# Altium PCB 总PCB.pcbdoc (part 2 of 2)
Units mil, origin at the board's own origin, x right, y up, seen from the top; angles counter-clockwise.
Board outline 1771.65 x 3543.31 mil, 2 copper layers (Top Layer, Bottom Layer), stack 62.205 mil thick; 115 components, 80 nets, 419 pads, 214 vias.
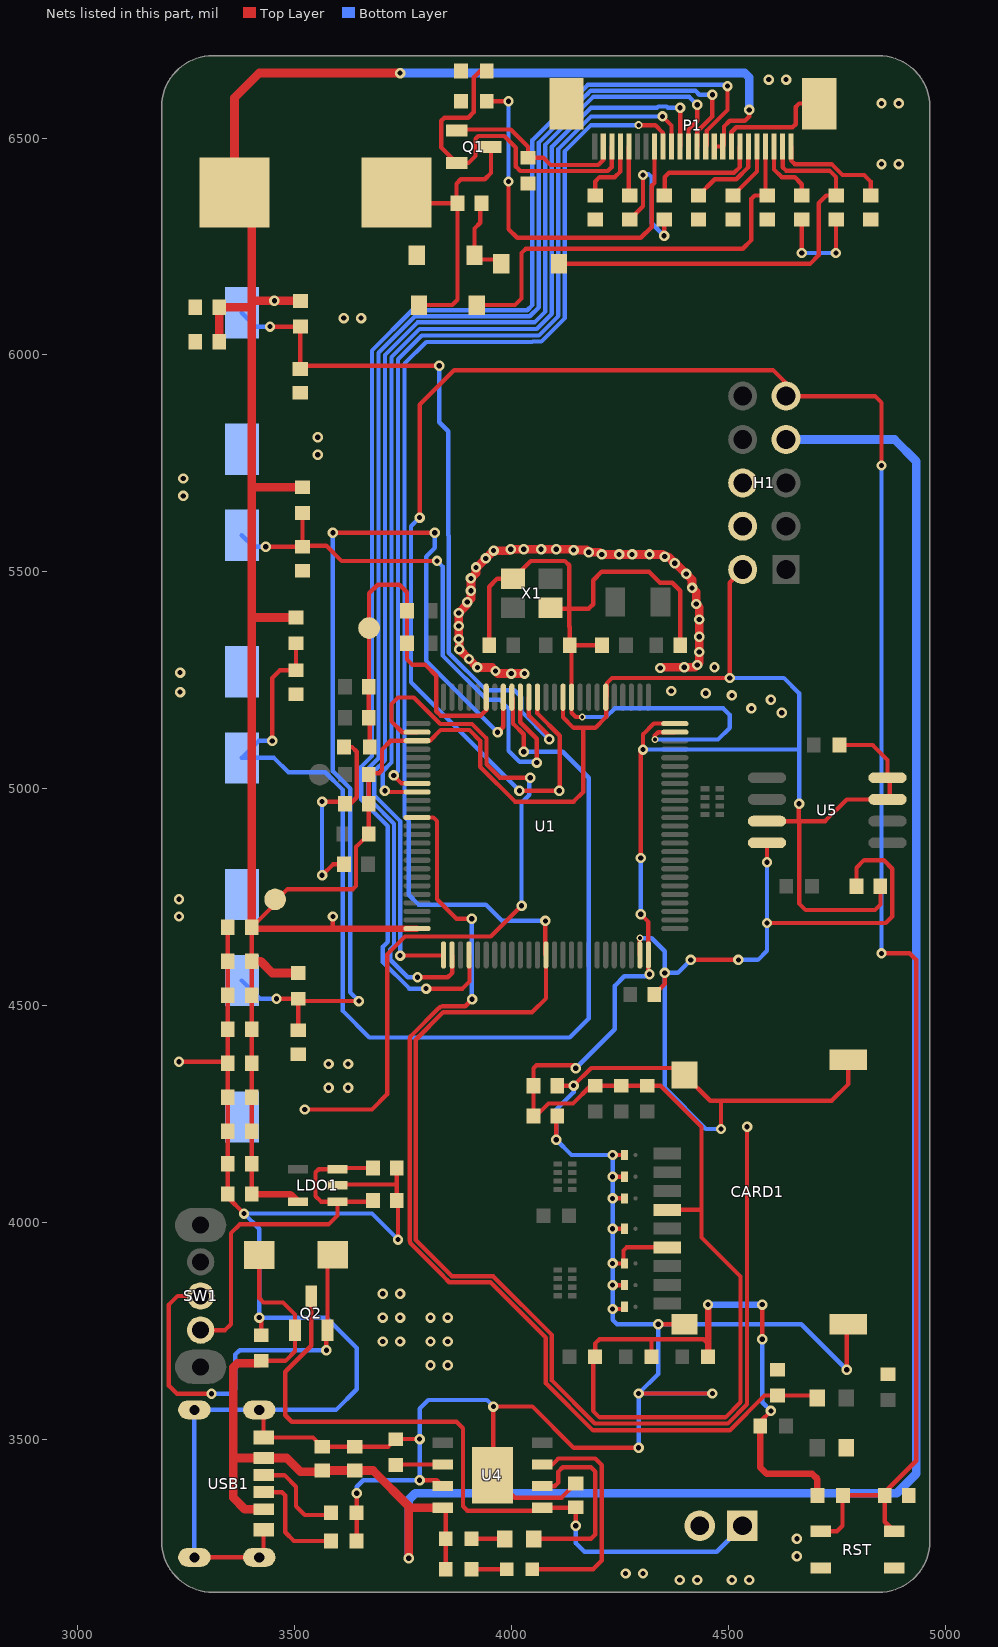
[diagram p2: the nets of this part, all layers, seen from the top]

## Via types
v1: diameter 24.02, hole 12.01, Top Layer to Bottom Layer, 210 vias
v2: diameter 16, hole 9, Top Layer to Bottom Layer, 3 vias
v3: diameter 18, hole 10, Top Layer to Bottom Layer, 1 vias

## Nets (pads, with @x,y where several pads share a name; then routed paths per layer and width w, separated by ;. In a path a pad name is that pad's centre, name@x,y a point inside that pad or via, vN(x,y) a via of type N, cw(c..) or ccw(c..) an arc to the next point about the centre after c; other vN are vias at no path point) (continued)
$1I11\NRST: C37.1 H1.9 R12.1 RST.3 RST.4 U1.14 | length 5412.9
  Top Layer w10: v1(3788.47,5625) 3788.47,5885 3868.47,5965 4603.47,5965 4633.47,5935 H1.9@4633.47,5905 4838.47,5905 4853.47,5890 v1(4853.47,5745) ; v1(4018.47,4995) v1(4110.54,4995) 4111.46,4995.92 4111.46,5122.01 4060.06,5173.41 U1.14@4060.06,5210.8 ; RST.4@4713.82,3287.32 4750.79,3287.32 4763.47,3300 4763.47,3368.55 R12.1@4765.02,3370.1 4860.8,3370.1 C37.1@4860.91,3370 ; v1(4853.47,4620) 4918.47,4620 4933.47,4605 4933.47,3450 4860.91,3377.44 C37.1@4860.91,3370 ; RST.3@4883.11,3287.32 4860.91,3309.53 C37.1@4860.91,3370
  Bottom Layer w10: v1(3788.47,5625) 3768.47,5605 3768.47,5245 v1(4018.47,4995) ; v1(4853.47,4620) v1(4853.47,5745)
$1I11\PB2(BOOT1): LED3.1 R18.2 U1.37 | length 2382.3
  Top Layer w10: U1.37@3782.51,4933.24 3820.23,4933.24 3828.47,4925 3828.47,4745 3873.47,4700 v1(3908.47,4700) ; v1(3909.45,4514.02) 3893.47,4498.03 3842.66,4498.03 ccw(c3842.66,4484.02) 3832.75,4493.93 3769.54,4430.72 ccw(c3779.45,4420.81) 3765.44,4420.81 3765.44,3959.19 ccw(c3779.45,3959.19) 3769.54,3949.28 3843.47,3875.36 3843.47,3875 3856.97,3861.5 3951.97,3861.5 4079.45,3734.02 4079.45,3629.02 4188.47,3520 4503.47,3520 4583.81,3600.34 R18.2@4613.47,3600.34 4699.66,3600.34 LED3.1@4705,3595
  Bottom Layer w10: v1(3908.47,4700) 3908.47,4515 v1(3909.45,4514.02)
$1I11\PC0: C38.2 R13.1 SW3.2 U1.15 | length 1690.1
  Top Layer w10: v1(3443.47,6065.34) R13.1@3513.47,6065.34 C38.2@3513.47,5967.56 3520.91,5975 v1(3833.47,5975) ; U1.15@4040.38,5210.8 4040.38,5168.09 4087.21,5121.26 v1(4087.21,5113.74)
  Bottom Layer w10: SW3.2@3378.47,6097.48 3410.61,6065.34 v1(3443.47,6065.34) ; v1(3833.47,5975) 3833.47,5845 3854.45,5824.02 3854.45,5584.19 3855.48,5583.17 3855.48,5312.99 3941.4,5227.07 4006.4,5227.07 4023.47,5210 4023.47,5177.48 v1(4087.21,5113.74)
$1I11\PC1: C39.2 R14.1 SW4.2 U1.16 | length 1320.6
  Top Layer w10: v1(3433.47,5557.56) C39.2@3518.47,5557.56 ; R14.1@3518.47,5635.34 C39.2@3518.47,5557.56 ; v1(3828.47,5525) 3608.47,5525 3573.47,5560 3520.91,5560 C39.2@3518.47,5557.56 ; U1.16@4020.69,5210.8 4020.69,5152.78 4058.47,5115 v1(4058.47,5060)
  Bottom Layer w10: SW4.2@3378.47,5584.15 3405.05,5557.56 v1(3433.47,5557.56) ; v1(3828.47,5525) 3841.46,5512.01 3841.46,5307.01 3943.47,5205 3973.47,5205 3993.47,5185 3993.47,5087.48 4018.94,5062.01 4056.46,5062.01 v1(4058.47,5060)
$1I11\PC2: C40.2 R15.1 SW5.2 U1.17 | length 2607.4
  Top Layer w10: v1(3448.47,5110) 3448.47,5255 3466.03,5272.56 C40.2@3503.47,5272.56 R15.1@3503.47,5335.34 ; U1.17@4001.01,5210.8 4003.8,5208.01 4003.8,5149.85 4028.47,5125.18 v1(4028.47,5085)
  Bottom Layer w10: v1(3448.47,5110) 3417.65,5110 SW5.2@3378.47,5070.81 3452.65,5070.81 3485.91,5037.56 3570.91,5037.56 3611.46,4997.01 3611.46,4487.01 3672.48,4425.98 4134.45,4425.98 4178.47,4470 4178.47,5025 4118.47,5085 v1(4028.47,5085)
$1I11\PC3: C41.2 R16.1 SW6.2 U1.18 | length 2325.5
  Top Layer w10: v1(3458.47,4515.34) R16.1@3508.47,4515.34 ; C41.2@3508.47,4442.56 R16.1@3508.47,4515.34 ; v1(3588.47,5590) v1(3823.47,5590) ; v1(3648.47,4510) 3513.81,4510 R16.1@3508.47,4515.34 ; v1(3968.24,5129.78) 3981.32,5142.85 U1.18@3981.32,5210.8
  Bottom Layer w10: SW6.2@3378.47,4557.48 3420.61,4515.34 v1(3458.47,4515.34) ; v1(3588.47,5590) 3588.47,5040 3628.47,5000 3628.47,4530 v1(3648.47,4510) ; v1(3823.47,5590) 3823.47,5555 3803.47,5535 3803.47,5294.55 v1(3968.24,5129.78)
$1I12\$1N70: C45.2 P1.24 | length 268.3
  Top Layer w10: P1.24@4645.1,6480.78 4645.1,6448.36 4653.47,6440 4738.47,6440 4763.47,6415 4813.47,6415 4828.47,6400 C45.2@4828.47,6367.56
$1I12\$1N71: C35.2 P1.22 | length 157.3
  Top Layer w10: P1.22@4605.71,6480.78 4605.71,6427.76 4623.47,6410 4653.47,6410 4669.72,6393.75 C35.2@4669.72,6367.56
$1I12\$1N72: C33.2 P1.20 | length 136.2
  Top Layer w10: C33.2@4510.97,6367.56 4566.34,6422.94 P1.20@4566.34,6480.78
$1I12\$1N73: C32.2 P1.19 | length 189.8
  Top Layer w10: C32.2@4431.59,6367.56 4469.03,6405 4518.47,6405 4546.57,6433.1 P1.19@4546.57,6480.78
$1I12\$1N74: C29.2 P1.18 | length 273.4
  Top Layer w10: C29.2@4352.22,6367.56 4353.47,6368.81 4353.47,6410 4363.47,6420 4513.47,6420 4526.89,6433.43 P1.18@4526.89,6480.78
$1I12\$1N84: C27.2 P1.5 | length 114
  Top Layer w10: P1.5@4271,6480.78 4271,6369.4 C27.2@4272.84,6367.56
$1I12\$1N85: C25.2 P1.4 | length 157.7
  Top Layer w10: C25.2@4193.47,6367.56 4193.47,6400 4203.47,6410 4238.47,6410 4251.32,6422.85 P1.4@4251.32,6480.78
$1I12\$1N94: C28.2 D4.2 L2.2 Q1.3 | length 663.7
  Top Layer w10: L2.2@3735.47,6375 3760.47,6350 C28.2@3875.91,6350 ; D4.2@3786.84,6115 3863.47,6115 3875.91,6127.44 C28.2@3875.91,6350 ; Q1.3@3952.84,6480 3952.84,6419.37 3938.47,6405 3883.47,6405 3873.47,6395 3873.47,6352.44 C28.2@3875.91,6350
$1I12\$1N95: C28.1 D2.2 D3.1 | length 196.6
  Top Layer w10: C28.1@3931.03,6350 3928.47,6347.44 3928.47,6305 3915.1,6291.63 D2.2@3915.1,6230 3925.1,6220 3966.84,6220 D3.1@3976.84,6210
$1I12\BS: P1.8 R3.2 | length 882.5
  Top Layer w10: R3.2@3943.13,6585 v1(3993.47,6585) ; v1(3993.47,6400) 3993.47,6290 4013.47,6270 4298.47,6270 4323.47,6295 4323.47,6390 4330.06,6396.6 P1.8@4330.06,6480.78
  Bottom Layer w10: v1(3993.47,6400) v1(3993.47,6585)
$1I12\BUS: P1.9 U1.63 | length 5296.9
  Top Layer w10: v1(4078.47,4695) 4078.47,4617.6 U1.63@4079.75,4616.32 4079.75,4516.28 4047.48,4484.02 3842.66,4484.02 3779.45,4420.81 3779.45,3959.19 3863.13,3875.51 3957.95,3875.51 4093.47,3740 4093.47,3635 4192.48,3535.98 4499.27,3535.98 4543.47,3580.18 v1(4543.47,4220) ; v3(4293.47,6530) 4331.81,6530 4349.74,6512.07 P1.9@4349.74,6480.78
  Bottom Layer w10: v1(4078.47,4695) 3978.47,4695 3940.97,4732.5 3785.97,4732.5 3763.47,4755 3763.47,4925 3753.47,4935 3753.47,5980 3803.47,6030 4048.47,6030 4049.45,6030.98 4069.27,6030.98 4123.47,6085.18 4123.47,6470 4183.47,6530 v3(4293.47,6530)
$1I12\CS: P1.12 U1.51 | length 2824.7
  Top Layer w10: v1(3743.47,4615) 3842.21,4615 U1.51@3843.53,4616.32 ; P1.12@4408.8,6480.78 4408.47,6481.12 4408.47,6520 4428.47,6540 v1(4428.47,6576.74)
  Bottom Layer w10: v1(3743.47,4615) 3743.47,4925 3683.47,4985 3683.47,5040 3708.47,5065 3708.47,6000 3783.47,6075 4053.47,6075 4078.47,6100 4078.47,6485 4188.47,6595 4410.2,6595 v1(4428.47,6576.74)
$1I12\D/C: P1.11 U1.34 | length 2306.6
  Top Layer w10: v1(3708.47,4995) 3711.17,4992.3 U1.34@3782.51,4992.3 ; P1.11@4389.11,6480.78 v1(4389.11,6570)
  Bottom Layer w10: v1(3708.47,4995) 3703.47,5000 3703.47,5040 3723.47,5060 3723.47,5995 3788.47,6060 4058.47,6060 4093.47,6095 4093.47,6480 4183.47,6570 4335.95,6570 4338.94,6572.99 4357.99,6572.99 4360.98,6570 v1(4389.11,6570)
$1I12\GDR: P1.2 Q1.1 R11.2 | length 424.1
  Top Layer w10: Q1.1@3874.1,6517.4 3876.7,6520 3998.47,6520 4038.47,6480 R11.2@4038.47,6454.66 4038.81,6455 4073.47,6455 4090.44,6438.03 4200.5,6438.03 4211.95,6449.49 P1.2@4211.95,6480.78
$1I12\PREVGH: C34.2 D4.1 P1.21 | length 1007
  Top Layer w10: D4.1@3920.1,6115 4008.47,6115 4023.47,6130 4023.47,6235 4033.47,6245 4533.47,6245 4553.47,6265 4553.47,6360 4561.03,6367.56 C34.2@4590.34,6367.56 4586.04,6371.86 P1.21@4586.04,6480.78
$1I12\PREVGL: C36.2 D3.2 P1.23 | length 997.6
  Top Layer w10: D3.2@4110.1,6210 4688.47,6210 4708.47,6230 4708.47,6350 4726.03,6367.56 C36.2@4749.09,6367.56 4748.47,6368.19 4748.47,6410 4733.47,6425 4633.47,6425 4625.41,6433.06 P1.23@4625.41,6480.78
$1I12\RES: P1.10 U1.33 | length 2170.6
  Top Layer w10: v1(3728.97,5030.51) 3728.97,5029.49 3746.48,5011.99 U1.33@3782.51,5011.99 ; v1(4348.47,6550) 4369.43,6529.03 P1.10@4369.43,6480.78
  Bottom Layer w10: v1(3728.97,5030.51) 3738.47,5040 3738.47,5990 3793.47,6045 4063.47,6045 4108.47,6090 4108.47,6475 4183.47,6550 v1(4348.47,6550)
$1I12\RESE: P1.3 Q1.2 R4.1 | length 828.5
  Top Layer w10: R4.1@3943.13,6655 3928.47,6655 3913.47,6640 3913.47,6560 3900.54,6547.07 3845.54,6547.07 3838.47,6540 3838.47,6478.23 Q1.2@3874.1,6442.6 3901.07,6442.6 3917.25,6458.78 3917.25,6498.33 3923.68,6504.76 3973.23,6504.76 3973.47,6505 3983.47,6505 4010.48,6477.99 4010.48,6434.23 4020.69,6424.02 4222.48,6424.02 4231.63,6433.16 P1.3@4231.63,6480.78
$1I12\SCK: P1.13 U1.52 | length 3023.6
  Top Layer w10: v1(3783.47,4565) 3853.47,4565 3863.47,4575 3863.47,4616.06 U1.52@3863.21,4616.32 ; P1.13@4428.48,6480.78 4428.48,6515.02 4463.47,6550 v1(4463.47,6600)
  Bottom Layer w10: v1(3783.47,4565) 3760.95,4565 3720.48,4605.48 3720.48,4628.89 3729.45,4637.87 3729.45,4919.02 3678.47,4970 3678.47,4970.18 3669.45,4979.19 3669.45,5045.81 3678.47,5054.82 3678.47,5055 3693.47,5070 3693.47,6005 3777.48,6089.02 4042.48,6089.02 4063.47,6110 4063.47,6490 4173.47,6600 4173.65,6600 4182.66,6609.02 4424.46,6609.02 4433.48,6600 v1(4463.47,6600)
$1I12\SDA: P1.14 U1.54 | length 3202.5
  Top Layer w10: v1(3803.47,4538.69) 3887.16,4538.69 3903.47,4555 3903.47,4615.43 U1.54@3902.58,4616.32 ; P1.14@4448.17,6480.78 4450.81,6483.43 4450.81,6517.35 4498.47,6565 v1(4498.47,6620)
  Bottom Layer w10: v1(3803.47,4538.69) 3764.78,4538.69 3703.47,4600 3703.47,4635 3715.25,4646.78 3715.25,4913.22 3653.47,4975 3653.47,5050 3678.47,5075 3678.47,6010 3771.5,6103.03 4036.5,6103.03 4048.47,6115 4048.47,6495 4176.46,6622.99 4495.48,6622.99 v1(4498.47,6620)
$1I13\$1N65: R6.1 USB1.B5 | length 251.8
  Top Layer w10: USB1.B5@3428.46,3377.52 3470.95,3377.52 3478.47,3370 3478.47,3285 3498.47,3265 R6.1@3583.81,3265
$1I13\$1N66: R7.1 USB1.A5 | length 221.8
  Top Layer w10: USB1.A5@3428.46,3416.89 3476.58,3416.89 3503.47,3390 3503.47,3345 3523.47,3325 3578.81,3325 R7.1@3583.81,3330
$1I13\$1N69: R5.2 U4.2 | length 109.8
  Top Layer w10: R5.2@3733.47,3445.34 3737.32,3441.49 U4.2@3841.69,3441.49
$1I13\$1N73: LED1.1 R8.2 | length 76.9
  Top Layer w10: R8.2@3908.13,3270 LED1.1@3985,3270
$1I13\$1N74: LED2.2 R9.2 | length 80.8
  Top Layer w10: R9.2@3908.13,3200 LED2.2@3988.98,3199.99
$1I13\$1N75: LED1.2 U4.6 | length 450.3
  Top Layer w10: LED1.2@4051.93,3270 4183.47,3270 4193.47,3280 4193.47,3425 4183.47,3435 4118.47,3435 4108.47,3425 4108.47,3400 4099.96,3391.49 U4.6@4070.69,3391.49
$1I13\$1N76: LED2.1 U4.7 | length 538.4
  Top Layer w10: LED2.1@4047.96,3200.01 4188.47,3200 4208.47,3220 4208.47,3440 4193.47,3455 4108.47,3455 4094.96,3441.49 U4.7@4070.69,3441.49
$1I13\NET_BAT: C26.2 CN1.1 Q2.3 U4.5 | length 1669.5
  Top Layer w10: Q2.3@3538.47,3829.37 3538.47,3715 3478.47,3655 3478.47,3555 3493.47,3540 3873.47,3540 3888.47,3525 3888.47,3345 3898.47,3335 4064.2,3335 U4.5@4070.69,3341.49 4147.52,3341.49 C26.2@4148.47,3342.44 v1(4148.47,3300)
  Bottom Layer w10: v1(4148.47,3300) 4148.47,3260 4168.47,3240 4473.47,3240 CN1.1@4533.47,3300
$1I13\VIN_RAM: D1.2 Q2.2 SW1.2 | length 954.2
  Top Layer w10: SW1.2@3283.46,3830 3230.28,3830 3210.28,3810 3210.28,3623.19 3229.08,3604.39 v1(3308.47,3604.39) ; v1(3573.47,3705) 3573.47,3748.23 Q2.2@3575.87,3750.63 3575.87,3913.12 D1.2@3588.11,3925.37
  Bottom Layer w10: v1(3308.47,3604.39) 3352.85,3604.39 3363.47,3615 3363.47,3695 3373.47,3705 v1(3573.47,3705)
$1I13\VOUT_RAM: C19.2 C20.2 LDO1.1 LDO1.3 SW1.3 | length 910.2
  Top Layer w10: SW1.3@3283.46,3751.26 3339.73,3751.26 3353.47,3765 3353.47,3975 3373.47,3995 3578.47,3995 3598.89,4015.42 LDO1.1@3598.89,4047.6 ; C20.2@3680.91,4050 3678.51,4047.6 LDO1.1@3598.89,4047.6 ; C19.2@3680.91,4125 3601.49,4125 LDO1.3@3598.89,4122.4 3555.87,4122.4 3548.47,4115 3548.47,4060 3560.87,4047.6 LDO1.1@3598.89,4047.6
+3V3: C7.1 C12.2 C13.2 C14.2 C15.2 C16.2 C17.2 C18.2 C21.2 C22.2 C30.2 C31.2 C42.1 C43.2 C44.1 CARD1.4 H1.2 L1.1 L2.1 LDO1.5 P1.15 P1.16 R1.1 R12.2 R13.2 R14.2 R15.2 R16.2 R19.2 R20.2 R21.2 R22.2 R23.2 R24.2 R26.2 R28.1 TP1.1 U1.6 U1.11 U1.28 U1.50 U1.75 U1.100 U5.3 U5.7 U5.8 | length 13102.6
  Top Layer w10: C22.2@3401.03,4065 C21.2@3401.03,4135 C18.2@3401.03,4210 C17.2@3401.03,4288.33 C16.2@3401.03,4366.67 C15.2@3401.03,4445 C14.2@3401.03,4523.33 C13.2@3401.03,4601.67 C12.2@3401.03,4680 3455.17,4734.14 TP1.1@3455.17,4744.65 ; TP1.1@3460.17,4744.65 3483.66,4768.14 3634.64,4768.14 3641.72,4775.21 3641.72,4865.55 R1.1@3671.38,4895.21 3671.47,4895.31 C7.1@3671.47,4965.21 3671.47,5035.21 3694.64,5035.21 3701.72,5042.29 3701.72,5090.21 3721.72,5110.21 3782.31,5110.21 U1.28@3782.51,5110.41 3782.92,5110 3811.88,5110 3836.88,5135 3903.47,5135 3928.47,5110 3928.47,5050 4008.47,4970 4143.47,4970 4165.54,4992.07 4165.54,5140 4143.47,5140 4119.12,5164.35 U1.11@4119.12,5210.8 ; v1(3588.47,4705) 3588.47,4678.35 3589.48,4677.34 3589.99,4676.83 ; U1.50@3781.99,4676.83 U1.50@3782.51,4677.34 ; v1(4148.47,4355) 4141.4,4362.07 4057.98,4362.07 4050.91,4355 C43.2@4050.91,4315 C42.1@4050.91,4245 4057.03,4245 4085.73,4273.7 4142.17,4273.7 4183.13,4314.66 R22.2@4193.47,4314.66 R23.2@4253.47,4314.66 R19.2@4313.47,4314.66 4343.81,4314.66 4438.47,4220 4438.47,4031.3 ; 4168.47,5140 4193.47,5140 4218.47,5165 4218.47,5209.88 U1.6@4217.55,5210.8 4220.34,5213.59 4220.34,5243.39 4231.95,5255 v1(4503.47,5255) 4503.47,5475 H1.2@4533.47,5505 ; v1(4298.47,4710) 4315.97,4692.5 U1.75@4315.97,4616.32 4315.97,4574.57 v1(4318.47,4572.07) ; v1(4298.47,4840) 4298.47,5085 v1(4303.47,5090) 4303.47,5125 4328.47,5150 4376.77,5150 U1.100@4376.99,5149.78 ; R20.2@4323.13,3690 4323.13,3725.94 4327.46,3730.27 ; CARD1.4@4359.81,4028.66 4435.83,4028.66 4438.47,4031.3 ; 4453.47,3720 4443.47,3730 4327.73,3730 4327.46,3730.27 ; P1.15@4467.7,6480.78 P1.16@4487.52,6480.78 4490.33,6483.6 4490.33,6526.87 4503.47,6540 4538.47,6540 4548.47,6550 v1(4548.47,6565) ; R28.1@4573.81,3530 4573.81,3540.34 v1(4598.47,3565) ; v1(4578.47,3730) v1(4578.47,3810) ; U5.3@4589.49,4925 4662.54,4925 ; v1(4663.47,4965) 4662.54,4964.08 4662.54,4925 ; R26.2@4756.55,5100.5 4832.97,5100.5 4867.45,5066.02 U5.8@4867.45,5025 ; C44.1@4851.03,4775 4851.03,4732.56 4838.47,4720 4678.47,4720 4663.47,4735 4663.47,4924.08 4662.54,4925 ; U5.7@4867.45,4975 4773.47,4975 4723.47,4925 4662.54,4925 ; U5.7@4872.45,4970 U5.8@4872.45,5020 ; 4327.46,3730.27 4203.13,3730.27 4193.13,3720.27 R24.2@4193.13,3690 4188.47,3685.34 4188.47,3565 4203.47,3550 4493.47,3550 4528.47,3585 4528.47,3875 4438.47,3965 4438.47,4031.3
  Top Layer w15: C22.2@3401.03,4065 3490.65,4065 LDO1.5@3508.05,4047.6 ; C12.2@3401.03,4680 3403.69,4677.34 3589.48,4677.34 ; 3589.99,4676.83 U1.50@3781.99,4676.83 ; R21.2@4453.13,3690 4453.47,3690.34 4453.47,3720 v1(4453.47,3810) ; R28.1@4573.81,3530 4573.47,3529.66 4573.47,3435 4588.47,3420 4693.47,3420 4705.7,3407.77 R12.2@4705.7,3370.1
  Top Layer w20: C31.2@3326.03,6030 C30.2@3326.03,6110 3396.27,6110 3401.03,6114.76 ; C13.2@3401.03,4601.67 3421.8,4601.67 3448.81,4574.66 R16.2@3508.47,4574.66 ; C12.2@3401.03,4680 3401.03,5393.92 ; R15.2@3503.47,5394.66 3401.77,5394.66 3401.03,5393.92 ; R13.2@3513.47,6124.66 3453.81,6124.66 v1(3453.47,6125) 3402.7,6125 3401.03,6123.33 ; R14.2@3518.47,5694.66 3401.63,5694.66 3401.03,5695.26 ; v1(3743.47,6650) 3418.47,6650 3361.46,6592.99 L2.1@3361.46,6375 3401.03,6335.43 3401.03,6123.33 ; 3401.03,5393.92 3401.03,5695.26 ; 3401.03,5695.26 3401.03,6114.76 ; 3401.03,6114.76 3401.03,6123.33
  Bottom Layer w10: v1(4148.47,4355) 4238.47,4445 4238.47,4545 4260.54,4567.07 4313.47,4567.07 v1(4318.47,4572.07) ; v1(4298.47,4710) v1(4298.47,4840) ; v1(4303.47,5090) 4662.41,5090 4663.47,5091.06 ; v1(4503.47,5255) 4628.47,5255 4663.47,5220 4663.47,5091.06 ; v1(4578.47,3730) 4578.47,3585 v1(4598.47,3565) ; v1(4663.47,4965) 4663.47,5091.06
  Bottom Layer w15: v1(4453.47,3810) v1(4578.47,3810)
  Bottom Layer w20: v1(3743.47,6650) 4538.47,6650 4548.47,6640 v1(4548.47,6565)
AGND: C5.1 C6.2 C10.2 C11.1 R2.2 TP3.1 U1.20 | length 932.7
  Top Layer w10: R2.2@3673.57,5095.87 3673.57,5161.47 C10.2@3671.47,5163.57 C11.1@3671.47,5235.21 3671.72,5235.46 TP3.1@3671.72,5370.21 3671.72,5450.21 3691.72,5470.21 3741.72,5470.21 3759.16,5452.77 C6.2@3759.16,5410.21 C5.1@3759.16,5335.21 ; C5.1@3759.16,5335.21 3759.22,5297.71 3771.72,5285.21 3801.72,5285.21 3826.64,5260.29 3826.64,5178.21 3836.53,5168.32 3929.26,5168.32 3941.95,5181 U1.20@3941.95,5210.8
GND: C1.1 C2.1 C3.1 C4.1 C7.2 C8.1 C9.1 C12.1 C13.1 C14.1 C15.1 C16.1 C17.1 C18.1 C19.1 C20.1 C21.1 C22.1 C23.1 C24.2 C25.1 C26.1 C27.1 C29.1 C30.1 C31.1 C32.1 C33.1 C34.1 C35.1 C36.1 C37.2 C38.1 C39.1 C40.1 C41.1 C42.2 C43.1 C44.2 C45.1 CARD1.6 CARD1.10 CARD1.11 CARD1.12 CARD1.13 CN1.2 D2.1 D5.2 D6.2 D7.2 D8.2 D9.2 D10.2 D11.2 H1.4 H1.6 LDO1.2 LED4.2 P1.17 P1.25 P1.26 R2.1 R3.1 R4.2 R5.1 R6.2 R7.2 R10.2 R11.1 R17.2 R18.1 RST.1 RST.2 SW3.1 SW4.1 SW5.1 SW6.1 U1.10 U1.27 U1.74 U1.99 U4.3 U4.9 U5.4 USB1.7 USB1.A12 USB1.B12 X1.2 X1.4 | length 16158.4
  Top Layer w10: v1(3233.47,4370) 3342.57,4370 C16.1@3345.91,4366.67 ; USB1.7@3269.01,3227.12 USB1.7@3418.61,3227.12 3428.46,3236.97 USB1.A12@3428.46,3290.91 ; C12.1@3345.91,4680 C13.1@3345.91,4601.67 C14.1@3345.91,4523.33 C15.1@3345.91,4445 C16.1@3345.91,4366.67 ; v1(3383.47,4020) 3345.91,4057.56 C22.1@3345.91,4065 C21.1@3345.91,4135 C18.1@3345.91,4210 C17.1@3345.91,4288.33 C16.1@3345.91,4366.67 ; v1(3418.47,3780) 3423.47,3775 R10.2@3423.47,3739.66 ; USB1.7@3418.61,3567.28 3428.46,3557.44 USB1.B12@3428.46,3503.5 3542.53,3503.5 C24.2@3563.47,3482.56 C23.1@3638.47,3482.56 3716.37,3482.56 R5.1@3733.47,3499.66 3733.81,3500 v1(3788.47,3500) ; v1(3523.47,4260) 3678.47,4260 3713.47,4295 3713.47,4617.52 3754.75,4658.8 3952.27,4658.8 v1(4023.47,4730) ; v1(3563.47,4800) 3588.68,4825.21 C9.1@3614.16,4825.21 ; v1(3563.47,4970) 3611.57,4970 C7.2@3616.35,4965.21 3628.68,4965.21 3643.47,4980 3643.47,5085 3632.59,5095.87 R2.1@3614.25,5095.87 ; LDO1.2@3598.89,4085 3600.89,4087 3736.03,4087 ; R6.2@3643.13,3265 R7.2@3643.13,3330 3643.47,3330.34 v1(3643.47,3375) ; C19.1@3736.03,4125 3736.03,4087 ; v1(3738.47,3960) 3738.47,4047.56 C20.1@3736.03,4050 3736.03,4087 ; U1.27@3782.51,5130.1 3748.37,5130.1 3723.47,5155 3723.47,5195 3738.47,5210 3775.03,5210 3836.01,5149.02 3909.27,5149.02 3942.48,5115.81 3942.48,5055.98 3973.47,5025 v1(4043.47,5025) ; v1(3788.47,3405) 3828.18,3405 U4.3@3841.69,3391.49 ; C2.1@3949.16,5330.21 3949.16,5465.69 3967.15,5483.68 X1.4@4003.41,5483.68 4044.73,5525 4123.47,5525 4133.47,5515 4133.47,5415 ; X1.2@4090.03,5416.75 4091.77,5415 4133.47,5415 ; v1(4103.47,4190) 4103.47,4242.44 C42.2@4106.03,4245 ; C43.1@4106.03,4315 v1(4143.47,4315) 4184.25,4355.78 4383.07,4355.78 CARD1.12@4399.18,4339.68 4458.86,4280 4481.36,4280 ; C26.1@4148.47,3397.56 4115.91,3365 4007.68,3365 U4.9@3956.19,3416.49 3958.47,3418.76 v1(3958.47,3575) 4048.47,3575 4143.47,3480 v1(4293.47,3480) ; v2(4163.47,5165) 4148.47,5165 4138.47,5175 4138.47,5210.46 U1.10@4138.81,5210.8 4138.81,5325.68 C1.1@4134.28,5330.21 ; C4.1@4209.16,5330.21 C1.1@4134.28,5330.21 ; v1(4233.47,3800) 4255.67,3800 D5.2@4260.67,3805 ; v1(4233.47,3855) D8.2@4260.67,3855 ; v1(4233.47,3905) D9.2@4260.67,3905 4258.47,3907.2 4258.47,3935 4265.52,3942.05 CARD1.6@4359.81,3942.05 ; v1(4233.47,3985) D11.2@4260.67,3985 ; v1(4233.47,4055) D10.2@4260.67,4055 ; v1(4233.47,4105) D6.2@4260.67,4105 ; v1(4233.47,4155) D7.2@4260.67,4155 ; C27.1@4272.84,6312.44 4303.47,6343.06 v1(4303.47,6415) ; v1(4293.47,3605) v1(4463.47,3605) ; U1.74@4296.29,4616.32 v2(4296.29,4655) ; C8.1@4329.28,4525.21 4353.47,4549.41 v1(4353.47,4575) ; v2(4330.81,5113.02) 4330.81,5122.44 4338.47,5130.1 U1.99@4376.99,5130.1 ; v1(4338.47,3764.88) CARD1.10@4399.18,3764.88 ; v1(4352.22,6275) C29.1@4352.22,6312.44 ; C3.1@4389.28,5330.21 4389.28,5456.46 4371.07,5474.66 4342.8,5474.66 4317.46,5500 4208.09,5500 4188.7,5480.61 4188.7,5425.23 4178.47,5415 4133.47,5415 ; v1(4413.47,4605) v1(4523.47,4605) ; v1(4483.47,4215) 4483.47,4277.89 4481.36,4280 ; P1.17@4507.22,6480.78 4507.22,6513.76 4518.47,6525 4648.47,6525 4655.54,6532.07 4655.54,6572.07 4663.47,6580 4709.06,6580 P1.25@4709.84,6579.22 ; v1(4589.49,4690) 4863.47,4690 4878.47,4705 4878.47,4815 4858.47,4835 4813.47,4835 4795.91,4817.44 C44.2@4795.91,4775 ; v1(4589.49,4830) U5.4@4589.49,4875 ; v1(4669.72,6235) C35.1@4669.72,6312.44 ; v1(4748.47,6235) 4748.47,6311.81 C36.1@4749.09,6312.44 ; v1(4773.47,3660) 4773.47,3761.22 CARD1.11@4777.13,3764.88 ; CARD1.13@4777.13,4375.12 4777.13,4318.66 4738.47,4280 4481.36,4280 ; 4133.47,5415 4133.47,5373.31 4134.28,5372.5 C1.1@4134.28,5330.21
  Top Layer w20: v1(4030.24,5265.21) v1(3999.53,5265.21) 3969.35,5265.21 v1(3963.44,5271.12) 3955.17,5279.39 v1(3921.59,5279.39) v1(3902.23,5298.76) v1(3879.73,5321.26) 3879.73,5343.74 v1(3878.47,5345) v1(3878.47,5375) v1(3878.47,5405) 3898.47,5425 v1(3898.47,5430) 3906.72,5438.25 v1(3906.72,5456.45) v1(3906.72,5484.64) 3918.47,5496.39 v1(3918.47,5510) 3920.28,5510 v1(3941.11,5530.82) v1(3959.01,5548.72) 3995.18,5548.72 v1(3998.47,5552.01) v1(4028.47,5552.01) v1(4068.47,5552.01) v1(4103.47,5552.01) 4141.46,5552.01 v1(4143.47,5550) 4173.47,5550 v1(4178.47,5545) 4203.47,5545 v1(4208.47,5540) v1(4248.47,5540) v1(4278.47,5540) v1(4318.47,5540) 4348.47,5540 v1(4353.47,5535) 4361.53,5535 v1(4376.72,5519.81) 4378.65,5519.81 v1(4403.47,5495) 4416.72,5481.75 v1(4416.72,5462.71) 4426.27,5453.16 v1(4426.27,5425.66) 4433.47,5418.46 v1(4433.47,5390) v1(4433.47,5350) v1(4433.47,5315) 4433.47,5290 v1(4428.47,5285) 4423.47,5280 v1(4398.47,5280) 4345.48,5280 v1(4343.47,5277.99)
  Bottom Layer w10: USB1.7@3269.01,3227.12 USB1.7@3269.01,3567.28 USB1.7@3418.61,3567.28 3595.74,3567.28 3643.47,3615 3643.47,3710 3573.47,3780 v1(3418.47,3780) 3418.47,3985 v1(3383.47,4020) 3678.47,4020 v1(3738.47,3960) ; v1(3563.47,4800) v1(3563.47,4970) ; v1(3643.47,3375) 3643.47,3390 3658.47,3405 v1(3788.47,3405) v1(3788.47,3500) 3788.47,3570 3808.47,3590 3943.47,3590 v1(3958.47,3575) ; v1(4023.47,4730) 4023.47,4967.48 4041.46,4985.48 4041.46,5022.99 v1(4043.47,5025) ; v1(4143.47,4315) 4143.47,4300 4103.47,4260 v1(4103.47,4190) 4138.47,4155 v1(4233.47,4155) v1(4233.47,4105) v1(4233.47,4055) v1(4233.47,3985) v1(4233.47,3905) v1(4233.47,3855) v1(4233.47,3800) 4233.47,3775 4243.59,3764.88 v1(4338.47,3764.88) ; v2(4163.47,5165) 4218.47,5165 4238.47,5185 4488.47,5185 4503.47,5170 4503.47,5140 4476.49,5113.02 v2(4330.81,5113.02) ; v1(4293.47,3480) v1(4293.47,3605) ; v2(4296.29,4655) 4323.47,4655 4353.47,4625 v1(4353.47,4575) ; v1(4303.47,6415) 4305.54,6417.07 4316.4,6417.07 4323.47,6410 4323.47,6303.75 v1(4352.22,6275) ; v1(4413.47,4605) 4383.47,4575 v1(4353.47,4575) ; v1(4463.47,3605) v1(4293.47,3605) ; v1(4483.47,4215) 4448.47,4215 4353.47,4310 v1(4353.47,4575) ; v1(4523.47,4605) 4568.47,4605 4589.49,4626.02 v1(4589.49,4690) v1(4589.49,4830) ; v1(4669.72,6235) v1(4748.47,6235) ; v1(4773.47,3660) 4668.59,3764.88 v1(4338.47,3764.88) ; v1(4293.47,3605) 4338.47,3650 v1(4338.47,3764.88)
  other v1: 4388.47,3175 4428.47,3175 4508.47,3175 4548.47,3175 4263.47,3190 4303.47,3190 4658.47,3230 4658.47,3270 3813.47,3670 3853.47,3670 3703.47,3725 3743.47,3725 3813.47,3725 3853.47,3725 3703.47,3780 3743.47,3780 3813.47,3780 3853.47,3780 3703.47,3835 3743.47,3835 3578.47,4310 3623.47,4310 3578.47,4365 3623.47,4365 3233.47,4705 3233.47,4745 4623.47,5175 4553.47,5185 4598.47,5205 4508.47,5215 4448.47,5220 3235.97,5222.5 4368.47,5225 3235.97,5267.5 4468.47,5280 3243.47,5675 3243.47,5715 3553.47,5770 3553.47,5810 3613.47,6085 3653.47,6085 4853.47,6440 4893.47,6440 4853.47,6580 4893.47,6580 4593.47,6635 4633.47,6635
VBUS_5V: C23.2 C24.1 D1.1 H1.7 Q2.1 R8.1 R9.1 R10.1 U4.4 USB1.A9 USB1.B9 | length 5606.6
  Top Layer w10: D1.1@3418.82,3924.63 3418.47,3924.28 3418.47,3825 3428.47,3815 3473.47,3815 3501.07,3787.4 Q2.1@3501.07,3750.63 3501.07,3702.6 3478.81,3680.34 R10.1@3423.47,3680.34 ; U4.4@3841.69,3341.49 3848.81,3334.37 R8.1@3848.81,3270 R9.1@3848.81,3200
  Top Layer w20: R10.1@3423.47,3680.34 3418.13,3675 3368.47,3675 3358.47,3665 3358.47,3460.53 ; USB1.A9@3428.46,3338.15 3385.32,3338.15 3358.47,3365 3358.47,3460.53 ; v1(3763.47,3225) 3763.47,3341.49 3766.98,3341.49 ; U4.4@3841.69,3341.49 3766.98,3341.49 ; 3358.47,3460.53 3362.74,3456.26 USB1.B9@3428.46,3456.26 3482.21,3456.26 3513.47,3425 3561.03,3425 C24.1@3563.47,3427.44 C23.2@3638.47,3427.44 3681.03,3427.44 3766.98,3341.49
  Bottom Layer w20: v1(3763.47,3225) 3763.47,3360 3778.47,3375 4888.47,3375 4933.47,3420 4933.47,5755 4883.47,5805 H1.7@4633.47,5805
pads on no net: LDO1.4 P1.1 P1.6 P1.7 RN2.4 RN2.5 SW1.1 SW1.4 SW1.5 U1.1 U1.2 U1.3 U1.4 U1.5 U1.7 U1.23 U1.24 U1.25 U1.26 U1.35 U1.36 U1.38 U1.39 U1.40 U1.41 U1.42 U1.43 U1.44 U1.45 U1.46 U1.47 U1.48 U1.53 U1.55 U1.56 U1.57 U1.58 U1.59 U1.60 U1.61 U1.62 U1.64 U1.67 U1.70 U1.71 U1.77 U1.81 U1.82 U1.85 U1.86 U1.87 U1.88 U1.90 U1.91 U1.92 U1.93 U1.95 U1.96 U1.97 U1.98 U4.1 U4.8

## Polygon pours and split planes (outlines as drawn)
GND on Top Layer (solid, remove dead copper, pour order 0): 3073.47,6815 5053.47,6815 5053.47,3025 3073.47,3025
GND on Bottom Layer (solid, remove dead copper, pour order 4): 3103.47,6805 5303.47,6805 5303.47,3000 3103.47,3000

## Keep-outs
Board Outline Layer:
  region: 3916.72,5265.21 3876.72,5305.21 3876.72,5415.21 3906.72,5445.21 3906.72,5496.43 3975.5,5565.21 4156.72,5565.21 4191.72,5530.21 4376.72,5530.21 4416.72,5490.21 4416.72,5435.21 4451.72,5400.21 4451.72,5285.21 4431.72,5265.21
  lines w10: 3193.47,3264.8 ccw(c3311.58,3264.8) 3311.58,3146.69 4847.01,3146.69 ccw(c4847.01,3264.8) 4965.12,3264.8 4965.12,6571.89 ccw(c4847.01,6571.89) 4847.01,6690 3311.58,6690 ccw(c3311.58,6571.89) 3193.47,6571.89 3193.47,3264.8

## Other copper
Top Layer:
  drawing of 642 lines, arcs and shapes, not listed
Bottom Layer:
  drawing of 157 lines, arcs and shapes, not listed

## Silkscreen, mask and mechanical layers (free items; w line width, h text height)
Top Silkscreen Layer:
  drawing of 46 lines, arcs and shapes, not listed
  text "TX" at 4308.47,5900 h45
  text "RST" at 4393.47,5895 h45
  text "RX" at 4308.47,5795 h45
  text "5V" at 4408.47,5795 h45
  text "GND" at 4298.47,5685 h45
  text "DIO" at 4403.47,5685 h45
  text "GND" at 4308.47,5580 h45
  text "CLK" at 4403.47,5580 h45
  text "3V3" at 4483.47,5420 h45
  text "SWO" at 4593.47,5420 h45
